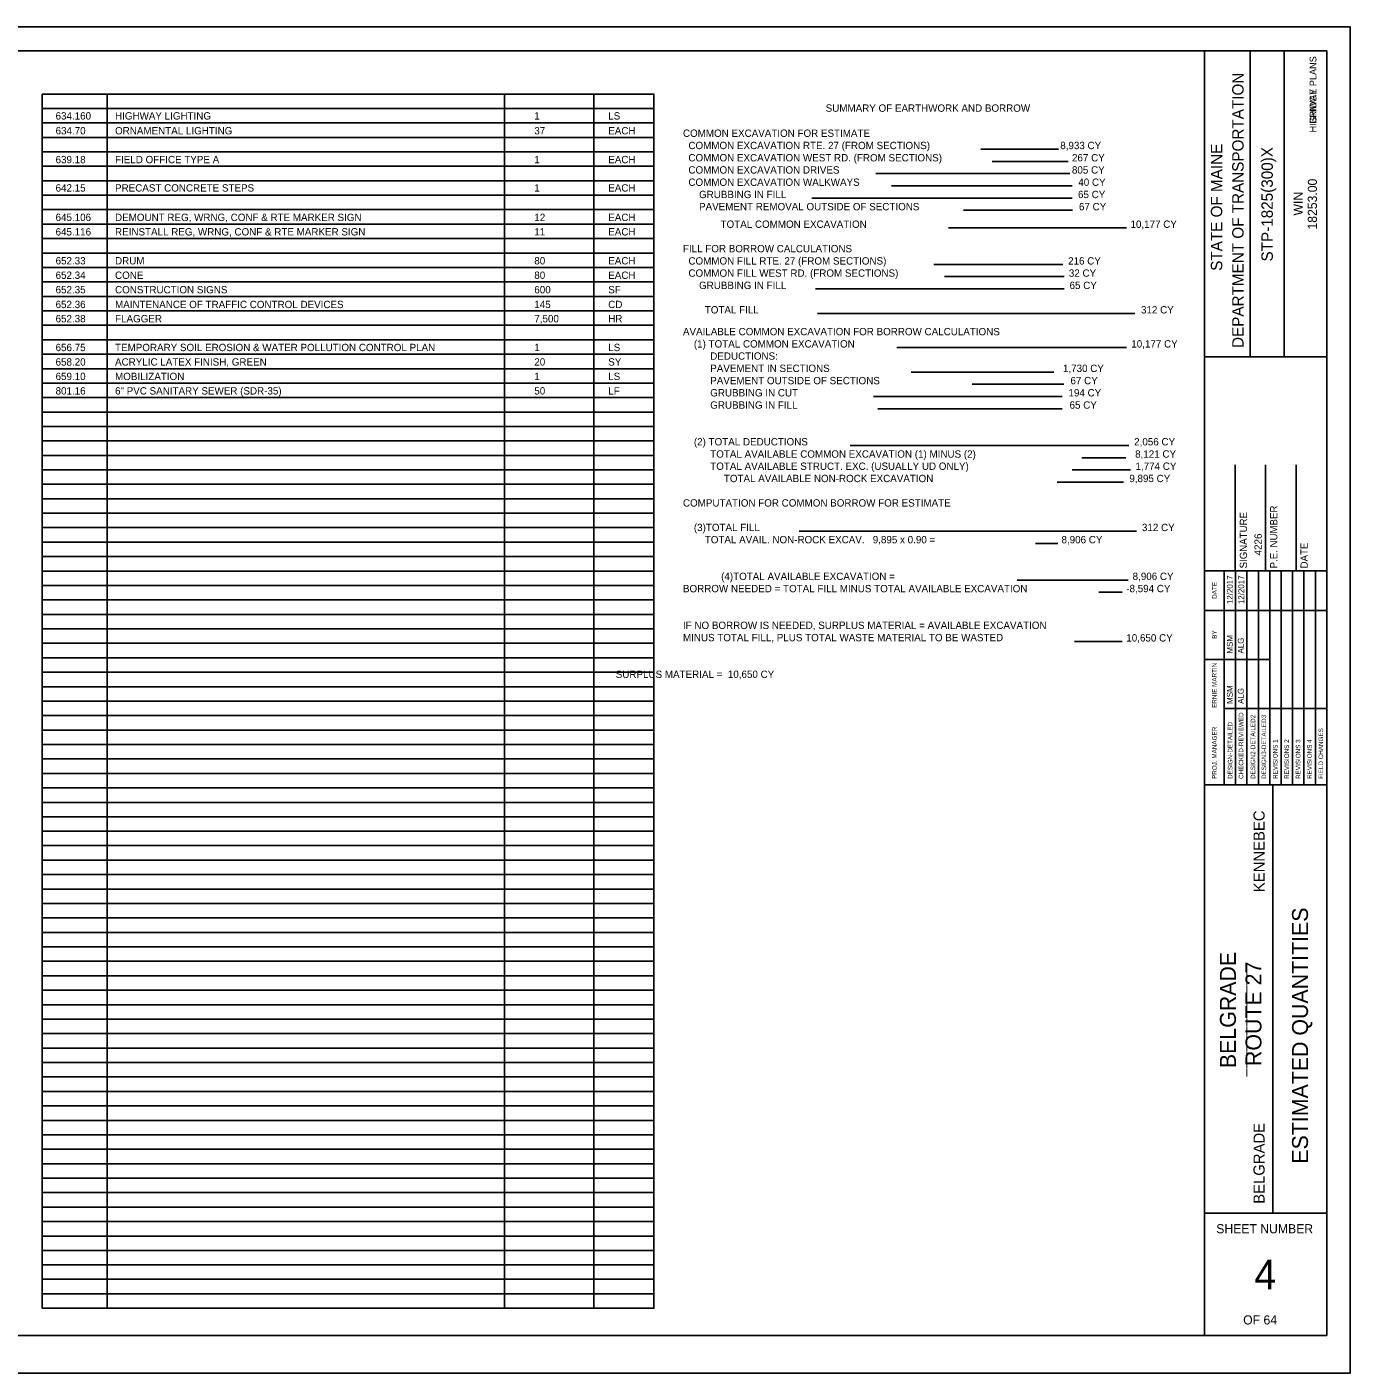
# Model space of a CAD drawing. Extents: x -0.13 to 2.7, y -0.05 to 1.78.
# Drawn here: x 0.896 to 2.698, y -0.051 to 1.782 of the extents above; entities that cross this region are included whole.
import ezdxf

# ---------------------------------------------------------------- set-up
doc = ezdxf.new("R2010")
doc.units = 0
for name, color, linetype in [('ANNOTATION', 7, 'Continuous'), ('BORDER', 7, 'Continuous'), ('BRIDGE_TITLE', 7, 'Continuous'), ('HIGHWAY_TITLE', 7, 'Continuous'), ('PLOT BOUNDARY', 7, 'Continuous')]:
    doc.layers.add(name, color=color, linetype=linetype)

msp = doc.modelspace()

# ---------------------------------------------------------------- linework, layer by layer
at = {"layer": 'ANNOTATION'}
for p, q in [((2.1954, 1.6158), (2.3014, 1.6158)), ((2.2107, 1.5992), (2.3145, 1.5992)), ((2.0522, 1.5825), (2.3168, 1.5825)), ((2.0739, 1.5659), (2.3197, 1.5659)), ((1.9653, 1.5492), (2.3197, 1.5492)), ((2.1716, 1.5326), (2.3203, 1.5326)), ((2.1512, 1.5087), (2.3937, 1.5087)), ((2.1312, 1.4589), (2.3071, 1.4589)), ((2.1459, 1.4424), (2.3089, 1.4424)), ((1.97, 1.4258), (2.3089, 1.4258)), ((1.9727, 1.392), (2.405, 1.392)), ((2.0808, 1.3458), (2.3938, 1.3458)), ((2.1005, 1.3123), (2.2948, 1.3123)), ((2.1836, 1.2956), (2.3083, 1.2956)), ((2.049, 1.2789), (2.3062, 1.2789)), ((2.055, 1.2623), (2.3062, 1.2623)), ((2.0175, 1.2124), (2.397, 1.2124)), ((2.333, 1.1957), (2.3931, 1.1957)), ((2.3197, 1.179), (2.3993, 1.179)), ((2.2995, 1.1625), (2.3898, 1.1625)), ((1.9478, 1.0957), (2.4074, 1.0957)), ((2.2697, 1.0789), (2.3002, 1.0789)), ((2.2451, 1.0291), (2.3959, 1.0291)), ((2.356, 1.0127), (2.3879, 1.0127)), ((2.3229, 0.9455), (2.3879, 0.9455))]:
    msp.add_line(p, q, dxfattribs=at)
at = {"layer": 'BORDER'}
for p, q in [((2.6667, 1.75), (0, 1.75)), ((2.5, 0), (2.5, 1.75)), ((2.5621, 1.3333), (2.5621, 1.75)), ((2.6087, 1.3333), (2.6087, 1.75)), ((2.6667, 0), (2.6667, 1.75)), ((0.9167, 1.6909), (1.75, 1.6909)), ((1.0052, 1.6909), (1.0052, 0.0373)), ((1.5466, 1.6909), (1.5466, 0.0373)), ((1.668, 1.6909), (1.668, 0.0373)), ((0.9167, 1.6713), (1.75, 1.6713)), ((0.9167, 1.6516), (1.75, 1.6516)), ((0.9167, 1.6319), (1.75, 1.6319)), ((0.9167, 1.6122), (1.75, 1.6122)), ((0.9167, 1.5925), (1.75, 1.5925)), ((0.9167, 1.5728), (1.75, 1.5728)), ((0.9167, 1.5531), (1.75, 1.5531)), ((0.9167, 1.5335), (1.75, 1.5335)), ((0.9167, 1.5138), (1.75, 1.5138)), ((0.9167, 1.4941), (1.75, 1.4941)), ((0.9167, 1.4744), (1.75, 1.4744)), ((0.9167, 1.4547), (1.75, 1.4547)), ((0.9167, 1.435), (1.75, 1.435)), ((0.9167, 1.4153), (1.75, 1.4153)), ((0.9167, 1.3957), (1.75, 1.3957)), ((0.9167, 1.376), (1.75, 1.376)), ((0.9167, 1.3563), (1.75, 1.3563)), ((0.9167, 1.3366), (1.75, 1.3366)), ((2.5, 1.3332), (2.6667, 1.3332)), ((0.9167, 1.3169), (1.75, 1.3169)), ((0.9167, 1.2972), (1.75, 1.2972)), ((0.9167, 1.2775), (1.75, 1.2775)), ((0.9167, 1.2579), (1.75, 1.2579)), ((0.9167, 1.2382), (1.75, 1.2382)), ((0.9167, 1.2185), (1.75, 1.2185)), ((0.9167, 1.1988), (1.75, 1.1988)), ((0.9167, 1.1791), (1.75, 1.1791)), ((2.5417, 1.0417), (2.5417, 1.1858)), ((2.5833, 1.0417), (2.5833, 1.1858)), ((2.625, 1.0417), (2.625, 1.1858)), ((0.9167, 1.1594), (1.75, 1.1594)), ((0.9167, 1.1397), (1.75, 1.1397)), ((0.9167, 1.12), (1.75, 1.12)), ((0.9167, 1.1004), (1.75, 1.1004)), ((0.9167, 1.0807), (1.75, 1.0807)), ((0.9167, 1.061), (1.75, 1.061)), ((0.9167, 1.0413), (1.75, 1.0413)), ((2.5, 1.0417), (2.6667, 1.0417)), ((0.9167, 1.0216), (1.75, 1.0216)), ((0.9167, 1.0019), (1.75, 1.0019)), ((0.9167, 0.9822), (1.75, 0.9822)), ((0.9167, 0.9626), (1.75, 0.9626)), ((0.9167, 0.9429), (1.75, 0.9429)), ((0.9167, 0.9232), (1.75, 0.9232)), ((0.9167, 0.9035), (1.75, 0.9035)), ((0.9167, 0.8838), (1.75, 0.8838)), ((0.9167, 0.8641), (1.75, 0.8641)), ((0.9167, 0.8444), (1.75, 0.8444)), ((0.9167, 0.8248), (1.75, 0.8248)), ((0.9167, 0.8051), (1.75, 0.8051)), ((0.9167, 0.7854), (1.75, 0.7854)), ((0.9167, 0.7657), (1.75, 0.7657)), ((0.9167, 0.746), (1.75, 0.746)), ((2.5, 0.75), (2.6667, 0.75)), ((2.5932, 0.1667), (2.5932, 0.75)), ((0.9167, 0.7263), (1.75, 0.7263)), ((0.9167, 0.7066), (1.75, 0.7066)), ((0.9167, 0.687), (1.75, 0.687)), ((0.9167, 0.6673), (1.75, 0.6673)), ((0.9167, 0.6476), (1.75, 0.6476)), ((0.9167, 0.6279), (1.75, 0.6279)), ((0.9167, 0.6082), (1.75, 0.6082)), ((0.9167, 0.5885), (1.75, 0.5885)), ((0.9167, 0.5688), (1.75, 0.5688)), ((0.9167, 0.5492), (1.75, 0.5492)), ((0.9167, 0.5295), (1.75, 0.5295)), ((0.9167, 0.5098), (1.75, 0.5098)), ((0.9167, 0.4901), (1.75, 0.4901)), ((0.9167, 0.4704), (1.75, 0.4704)), ((0.9167, 0.4507), (1.75, 0.4507)), ((0.9167, 0.431), (1.75, 0.431)), ((0.9167, 0.4114), (1.75, 0.4114)), ((0.9167, 0.3917), (1.75, 0.3917)), ((0.9167, 0.372), (1.75, 0.372)), ((0.9167, 0.3523), (1.75, 0.3523)), ((0.9167, 0.3326), (1.75, 0.3326)), ((0.9167, 0.3129), (1.75, 0.3129)), ((0.9167, 0.2932), (1.75, 0.2932)), ((0.9167, 0.2736), (1.75, 0.2736)), ((0.9167, 0.2539), (1.75, 0.2539)), ((0.9167, 0.2342), (1.75, 0.2342)), ((0.9167, 0.2145), (1.75, 0.2145)), ((0.9167, 0.1948), (1.75, 0.1948)), ((0.9167, 0.1751), (1.75, 0.1751)), ((2.5, 0.1667), (2.6667, 0.1667)), ((0.9167, 0.1554), (1.75, 0.1554)), ((0.9167, 0.1357), (1.75, 0.1357)), ((0.9167, 0.1161), (1.75, 0.1161)), ((0.9167, 0.0964), (1.75, 0.0964)), ((0.9167, 0.0767), (1.75, 0.0767)), ((0.9167, 0.057), (1.75, 0.057)), ((0, 0), (2.6667, 0))]:
    msp.add_line(p, q, dxfattribs=at)
msp.add_lwpolyline([(0.9167, 1.6909), (1.75, 1.6909), (1.75, 0.0373), (0.9167, 0.0373)], close=True, dxfattribs=at)
for points in [[(2.5269, 0.9875), (2.5269, 1.0417)], [(2.5269, 0.7501), (2.5269, 1.0299)], [(2.5425, 0.7501), (2.5425, 1.0417)], [(2.558, 1.0417), (2.558, 0.7501)], [(2.5735, 0.7501), (2.5735, 1.0417)], [(2.589, 0.7501), (2.589, 1.0417)], [(2.6046, 0.7501), (2.6046, 1.0417)], [(2.6201, 0.7501), (2.6201, 1.0417)], [(2.6356, 0.7501), (2.6356, 1.0417)], [(2.6512, 0.7501), (2.6512, 1.0417)], [(2.5, 0.9875), (2.6667, 0.9875)], [(2.5, 0.9209), (2.5269, 0.9209)], [(2.5269, 0.9209), (2.589, 0.9209)], [(2.5269, 0.8542), (2.6667, 0.8542)]]:
    msp.add_lwpolyline(points, dxfattribs=at)
at = {"layer": 'PLOT BOUNDARY'}
msp.add_lwpolyline([(-0.1349, -0.051), (2.6984, -0.051), (2.6984, 1.7823), (-0.1349, 1.7823)], close=True, dxfattribs=at)

# ---------------------------------------------------------------- texts
at = {"layer": 'ANNOTATION'}
for s, p in [('SUMMARY OF EARTHWORK AND BORROW', (1.984, 1.6668)), ('634.160', (0.9349, 1.6562)), ('HIGHWAY LIGHTING', (1.0159, 1.6562)), ('1', (1.5871, 1.6562)), ('LS', (1.6878, 1.6562)), ('634.70', (0.9349, 1.636)), ('ORNAMENTAL LIGHTING', (1.0159, 1.636)), ('37', (1.5871, 1.636)), ('EACH', (1.6878, 1.636)), ('COMMON EXCAVATION FOR ESTIMATE', (1.7896, 1.6326)), ('  COMMON EXCAVATION RTE. 27 (FROM SECTIONS)', (1.7896, 1.6159)), ('8,933 CY', (2.3036, 1.6159)), ('639.18', (0.9349, 1.5967)), ('FIELD OFFICE TYPE A', (1.0159, 1.5967)), ('1', (1.5871, 1.5967)), ('EACH', (1.6878, 1.5967)), ('  COMMON EXCAVATION WEST RD. (FROM SECTIONS)', (1.7896, 1.5992)), ('267 CY', (2.3196, 1.5992)), ('  COMMON EXCAVATION DRIVES', (1.7896, 1.5826)), ('805 CY', (2.3195, 1.5826)), ('642.15', (0.9349, 1.5581)), ('PRECAST CONCRETE STEPS', (1.0159, 1.5581)), ('1', (1.5871, 1.5581)), ('EACH', (1.6878, 1.5581)), ('  COMMON EXCAVATION WALKWAYS', (1.7896, 1.5659)), ('GRUBBING IN FILL', (1.8115, 1.5492)), ('40 CY', (2.3282, 1.5659)), ('65 CY', (2.3278, 1.5492)), ('PAVEMENT REMOVAL OUTSIDE OF SECTIONS', (1.8115, 1.5326)), ('67 CY', (2.3291, 1.5326)), ('645.106', (0.9349, 1.518)), ('DEMOUNT REG, WRNG, CONF & RTE MARKER SIGN', (1.0159, 1.518)), ('12', (1.5871, 1.518)), ('EACH', (1.6878, 1.518)), ('645.116', (0.9349, 1.4983)), ('REINSTALL REG, WRNG, CONF & RTE MARKER SIGN', (1.0159, 1.4983)), ('11', (1.5871, 1.4983)), ('EACH', (1.6878, 1.4983)), ('           TOTAL COMMON EXCAVATION', (1.8, 1.5087)), ('10,177 CY', (2.3993, 1.5087)), ('FILL FOR BORROW CALCULATIONS', (1.7896, 1.4754)), ('652.33', (0.9349, 1.4589)), ('DRUM', (1.0159, 1.4589)), ('80', (1.5871, 1.4589)), ('EACH', (1.6878, 1.4589)), ('  COMMON FILL RTE. 27 (FROM SECTIONS)', (1.7896, 1.4587)), ('216 CY', (2.3143, 1.4587)), ('652.34', (0.9349, 1.4392)), ('CONE', (1.0159, 1.4392)), ('80', (1.5871, 1.4392)), ('EACH', (1.6878, 1.4392)), ('  COMMON FILL WEST RD. (FROM SECTIONS)', (1.7896, 1.4421)), ('32 CY', (2.3153, 1.4421)), ('GRUBBING IN FILL', (1.8115, 1.4254)), ('65 CY', (2.3163, 1.4254)), ('652.35', (0.9349, 1.4195)), ('CONSTRUCTION SIGNS', (1.0159, 1.4195)), ('600', (1.5871, 1.4195)), ('SF', (1.6878, 1.4195)), ('652.36', (0.9349, 1.3994)), ('MAINTENANCE OF TRAFFIC CONTROL DEVICES', (1.0159, 1.3994)), ('145', (1.5871, 1.3994)), ('CD', (1.6878, 1.3994)), ('        TOTAL FILL', (1.7896, 1.3921)), ('312 CY', (2.4136, 1.3921)), ('652.38', (0.9349, 1.38)), ('FLAGGER', (1.0159, 1.38)), ('7,500', (1.5871, 1.38)), ('HR', (1.6878, 1.38)), ('AVAILABLE COMMON EXCAVATION FOR BORROW CALCULATIONS', (1.7896, 1.3624)), ('656.75', (0.9349, 1.3408)), ('TEMPORARY SOIL EROSION & WATER POLLUTION CONTROL PLAN', (1.0159, 1.3408)), ('1', (1.5871, 1.3408)), ('LS', (1.6878, 1.3408)), ('    (1) TOTAL COMMON EXCAVATION', (1.7896, 1.3457)), ('          DEDUCTIONS:', (1.7896, 1.3291)), ('10,177 CY', (2.4004, 1.3457)), ('658.20', (0.9349, 1.3211)), ('ACRYLIC LATEX FINISH, GREEN', (1.0159, 1.3211)), ('20', (1.5871, 1.3211)), ('SY', (1.6878, 1.3211)), ('          PAVEMENT IN SECTIONS', (1.7896, 1.3124)), ('1,730 CY', (2.3073, 1.3124)), ('659.10', (0.9349, 1.3014)), ('MOBILIZATION', (1.0159, 1.3014)), ('1', (1.5871, 1.3014)), ('LS', (1.6878, 1.3014)), ('          PAVEMENT OUTSIDE OF SECTIONS', (1.7896, 1.2957)), ('67 CY', (2.3175, 1.2957)), ('801.16', (0.9349, 1.2817)), ('6" PVC SANITARY SEWER (SDR-35)', (1.0159, 1.2817)), ('50', (1.5871, 1.2817)), ('LF', (1.6878, 1.2817)), ('          GRUBBING IN CUT', (1.7896, 1.2791)), ('194 CY', (2.3148, 1.2791)), ('          GRUBBING IN FILL', (1.7896, 1.2624)), ('65 CY', (2.3163, 1.2624)), ('    (2) TOTAL DEDUCTIONS', (1.7896, 1.2124)), ('2,056 CY', (2.4043, 1.2124)), ('          TOTAL AVAILABLE COMMON EXCAVATION (1) MINUS (2)', (1.7896, 1.1957)), ('8,121 CY', (2.4056, 1.1957)), ('          TOTAL AVAILABLE STRUCT. EXC. (USUALLY UD ONLY)', (1.7896, 1.1791)), ('1,774 CY', (2.4061, 1.1791)), ('               TOTAL AVAILABLE NON-ROCK EXCAVATION', (1.7896, 1.1624)), ('9,895 CY', (2.3977, 1.1624)), ('COMPUTATION FOR COMMON BORROW FOR ESTIMATE', (1.7896, 1.1291)), ('    (3)TOTAL FILL', (1.7896, 1.0957)), ('312 CY', (2.4149, 1.0957)), ('        TOTAL AVAIL. NON-ROCK EXCAV.   9,895 x 0.90 =', (1.7896, 1.0791)), ('8,906 CY', (2.3053, 1.0791)), ('              (4)TOTAL AVAILABLE EXCAVATION =', (1.7896, 1.0291)), ('8,906 CY', (2.4022, 1.0291)), ('BORROW NEEDED = TOTAL FILL MINUS TOTAL AVAILABLE EXCAVATION', (1.7896, 1.0124)), ('-8,594 CY', (2.3935, 1.0125)), ('IF NO BORROW IS NEEDED, SURPLUS MATERIAL = AVAILABLE EXCAVATION', (1.7896, 0.9624)), ('MINUS TOTAL FILL, PLUS TOTAL WASTE MATERIAL TO BE WASTED', (1.7896, 0.9457)), ('10,650 CY', (2.3936, 0.9453)), ('                                          SURPLUS MATERIAL =  10,650 CY', (1.542, 0.8957))]:
    msp.add_text(s, height=0.01, dxfattribs=at).set_placement(p)
msp.add_text('4226', height=0.01, rotation=90, dxfattribs=at).set_placement((2.5781, 1.0626))
at = {"layer": 'BORDER'}
for s, height, p in [('DEPARTMENT OF TRANSPORTATION', 0.015529, (2.5534, 1.3451)), ('STATE OF MAINE', 0.015529, (2.5243, 1.4502)), ('STP-1825(300)X', 0.015529, (2.5932, 1.4629)), ('18253.00', 0.01242, (2.6533, 1.5064)), ('WIN', 0.01242, (2.6339, 1.5255)), ('SIGNATURE', 0.00984, (2.558, 1.0449)), ('P.E. NUMBER', 0.009843, (2.5993, 1.0449)), ('DATE', 0.00984, (2.6407, 1.0449)), ('12/2017', 0.00808, (2.5387, 0.9963)), ('12/2017', 0.00808, (2.5542, 0.9963)), ('DATE', 0.00619, (2.5167, 1.0035)), ('BY', 0.00619, (2.5167, 0.949)), ('MSM', 0.00808, (2.5387, 0.929)), ('ALG', 0.00808, (2.5536, 0.929)), ('ERNIE MARTIN', 0.006212, (2.5167, 0.8549)), ('MSM', 0.00808, (2.5387, 0.8604)), ('ALG', 0.00808, (2.5536, 0.8604)), ('CHECKED-REVIEWED', 0.006212, (2.553, 0.7582)), ('PROJ. MANAGER', 0.006212, (2.5167, 0.7582)), ('DESIGN-DETAILED', 0.006212, (2.5381, 0.7582)), ('DESIGN2-DETAILED2', 0.006212, (2.5692, 0.7582)), ('DESIGN3-DETAILED3', 0.006212, (2.5841, 0.7582)), ('REVISIONS 1', 0.006212, (2.5996, 0.7582)), ('REVISIONS 2', 0.006212, (2.6151, 0.7582)), ('REVISIONS 3', 0.006212, (2.6307, 0.7582)), ('REVISIONS 4', 0.006212, (2.6462, 0.7582)), ('FIELD CHANGES', 0.006212, (2.6617, 0.7582)), ('ESTIMATED QUANTITIES', 0.021738, (2.6411, 0.2342))]:
    msp.add_text(s, height=height, rotation=90, dxfattribs=at).set_placement(p)
for s, height, p in [('SHEET NUMBER', 0.012421, (2.5161, 0.1394)), ('4', 0.0403, (2.5679, 0.063)), ('OF 64', 0.01242, (2.5528, 0.0152))]:
    msp.add_text(s, height=height, dxfattribs=at).set_placement(p)
at = {"layer": 'BRIDGE_TITLE'}
for s, height, p in [('BRIDGE PLANS', 0.009317, (2.6526, 1.6504)), ('KENNEBEC', 0.01512, (2.582, 0.604)), ('_____________', 0.015119, (2.5541, 0.3532)), ('BELGRADE', 0.01512, (2.582, 0.1796))]:
    msp.add_text(s, height=height, rotation=90, dxfattribs=at).set_placement(p)
at = {"layer": 'HIGHWAY_TITLE'}
for s, height, p in [('HIGHWAY PLANS', 0.009317, (2.6526, 1.6386)), ('BELGRADE', 0.02174, (2.5429, 0.3643)), ('ROUTE 27', 0.02174, (2.5777, 0.3672))]:
    msp.add_text(s, height=height, rotation=90, dxfattribs=at).set_placement(p)

doc.saveas('drawing.dxf')
